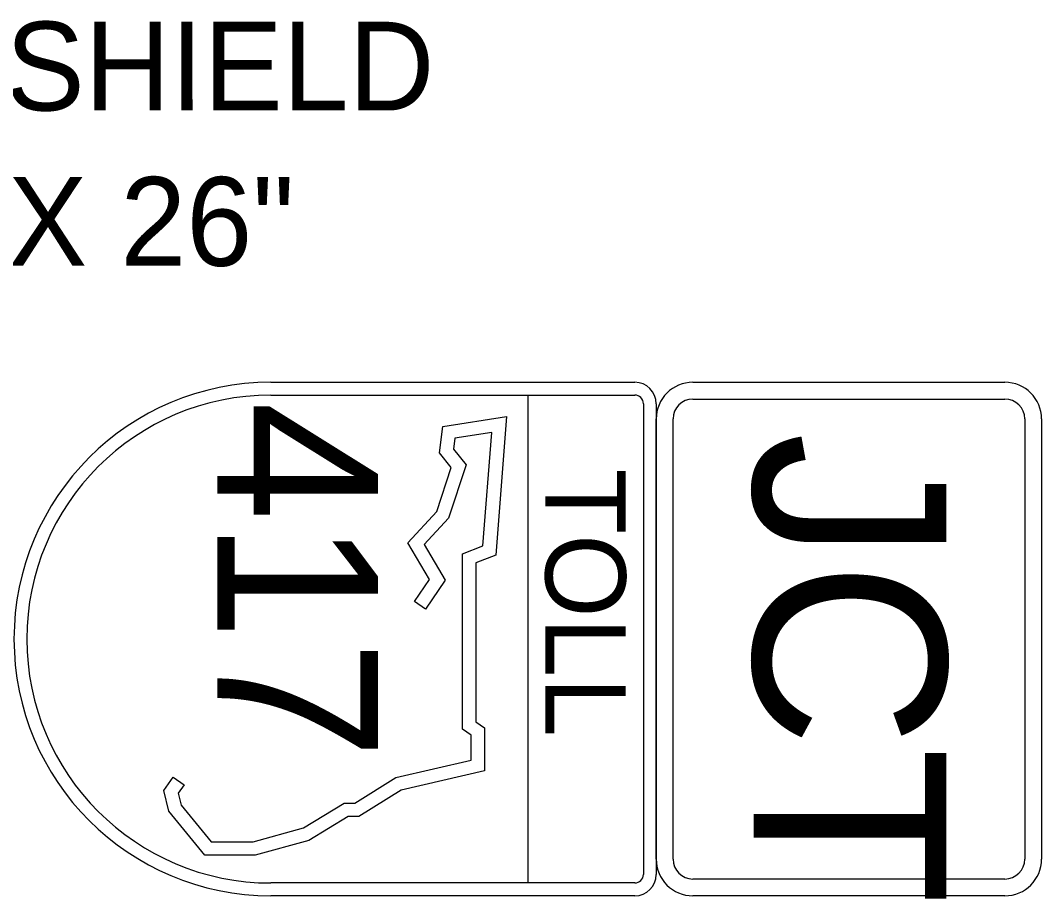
# Model space of a CAD drawing. Extents: x -830008.4 to -829992.7, y 1290284.1 to 1290294.4.
# Drawn here: x -830006.521 to -830005.716, y 1290287.565 to 1290288.258 of the extents above; entities that cross this region are included whole.
import ezdxf

# ---------------------------------------------------------------- set-up
doc = ezdxf.new("R2010")
doc.units = 0
doc.layers.add('1', color=7, linetype='Continuous')
doc.layers.add('SheetBorder_dp', color=7, linetype='Continuous')

msp = doc.modelspace()

# ---------------------------------------------------------------- linework, layer by layer
at = {"layer": 'SheetBorder_dp'}
for p, q in [((-830006.18833, 1290287.9375), (-830006.1383, 1290287.94528)), ((-830006.1383, 1290287.94528), (-830006.14674, 1290287.83592)), ((-830006.19091, 1290287.91656), (-830006.18833, 1290287.9375)), ((-830006.17884, 1290287.9283), (-830006.17991, 1290287.91963)), ((-830006.14984, 1290287.93281), (-830006.17884, 1290287.9283)), ((-830006.15675, 1290287.84335), (-830006.14984, 1290287.93281)), ((-830006.17991, 1290287.91963), (-830006.17013, 1290287.9072)), ((-830006.1819, 1290287.90511), (-830006.19091, 1290287.91656)), ((-830006.19317, 1290287.87048), (-830006.1819, 1290287.90511)), ((-830006.17013, 1290287.9072), (-830006.18385, 1290287.86501)), ((-830006.21611, 1290287.84572), (-830006.19317, 1290287.87048)), ((-830006.18385, 1290287.86501), (-830006.20304, 1290287.84431)), ((-830006.19901, 1290287.81663), (-830006.21611, 1290287.84572)), ((-830006.20304, 1290287.84431), (-830006.18654, 1290287.81623)), ((-830006.17302, 1290287.83702), (-830006.15675, 1290287.84335)), ((-830006.17302, 1290287.69877), (-830006.17302, 1290287.83702)), ((-830006.14674, 1290287.83592), (-830006.16247, 1290287.8298)), ((-830006.16247, 1290287.8298), (-830006.16247, 1290287.70437)), ((-830006.21073, 1290287.79929), (-830006.19901, 1290287.81663)), ((-830006.18654, 1290287.81623), (-830006.20199, 1290287.79338)), ((-830006.20199, 1290287.79338), (-830006.21073, 1290287.79929)), ((-830006.16247, 1290287.70437), (-830006.15548, 1290287.69964)), ((-830006.16603, 1290287.69404), (-830006.17302, 1290287.69877)), ((-830006.16603, 1290287.67427), (-830006.16603, 1290287.69404)), ((-830006.15548, 1290287.69964), (-830006.15548, 1290287.66589)), ((-830006.22532, 1290287.66049), (-830006.16603, 1290287.67427)), ((-830006.4083, 1290287.65036), (-830006.40109, 1290287.66076)), ((-830006.40109, 1290287.66076), (-830006.39242, 1290287.65475)), ((-830006.25766, 1290287.64036), (-830006.22532, 1290287.66049)), ((-830006.15548, 1290287.66589), (-830006.22123, 1290287.65061)), ((-830006.39242, 1290287.65475), (-830006.39695, 1290287.64823)), ((-830006.40437, 1290287.63395), (-830006.4083, 1290287.65036)), ((-830006.39695, 1290287.64823), (-830006.39468, 1290287.63876)), ((-830006.22123, 1290287.65061), (-830006.25465, 1290287.62981)), ((-830006.39468, 1290287.63876), (-830006.37107, 1290287.60996)), ((-830006.29828, 1290287.62078), (-830006.26604, 1290287.64036)), ((-830006.26604, 1290287.64036), (-830006.25766, 1290287.64036)), ((-830006.37606, 1290287.59941), (-830006.40437, 1290287.63395)), ((-830006.26309, 1290287.62981), (-830006.29407, 1290287.611)), ((-830006.25465, 1290287.62981), (-830006.26309, 1290287.62981)), ((-830006.33787, 1290287.60996), (-830006.29828, 1290287.62078)), ((-830006.37107, 1290287.60996), (-830006.33787, 1290287.60996)), ((-830006.29407, 1290287.611), (-830006.33645, 1290287.59941)), ((-830006.33645, 1290287.59941), (-830006.37606, 1290287.59941))]:
    msp.add_line(p, q, dxfattribs=at)
for points in [[(-830006.32393, 1290287.97228), (-830006.03705, 1290287.97228)], [(-830005.99125, 1290287.97228), (-830005.74536, 1290287.97228)], [(-830006.32393, 1290287.96216), (-830006.03705, 1290287.96216)], [(-830006.12143, 1290287.96216), (-830006.12143, 1290287.57741)], [(-830005.99125, 1290287.95903), (-830005.74534, 1290287.95903)], [(-830006.0303, 1290287.95541), (-830006.0303, 1290287.58416)], [(-830006.02018, 1290287.95541), (-830006.02018, 1290287.58416)], [(-830006.02018, 1290287.59621), (-830006.02018, 1290287.94336)], [(-830006.00692, 1290287.59621), (-830006.00692, 1290287.94336)], [(-830005.72969, 1290287.94336), (-830005.72969, 1290287.59621)], [(-830005.71643, 1290287.94336), (-830005.71643, 1290287.59621)], [(-830005.74534, 1290287.58054), (-830005.99125, 1290287.58054)], [(-830006.03705, 1290287.57741), (-830006.32393, 1290287.57741)], [(-830006.03705, 1290287.56728), (-830006.32393, 1290287.56728)], [(-830005.74536, 1290287.56728), (-830005.99125, 1290287.56728)]]:
    msp.add_lwpolyline(points, dxfattribs=at)
for centre, radius, start, end in [((-830006.32393, 1290287.76978), 0.2025, 90, 270), ((-830006.03705, 1290287.95541), 0.01687, 0, 90), ((-830005.99125, 1290287.94336), 0.02893, 90, 180), ((-830005.74536, 1290287.94336), 0.02893, 0, 90), ((-830006.32393, 1290287.76978), 0.19238, 90, 270), ((-830006.03705, 1290287.95541), 0.00675, 0, 90), ((-830005.99125, 1290287.94336), 0.01567, 90, 180), ((-830005.74536, 1290287.94336), 0.01567, 0, 89.9456), ((-830005.99125, 1290287.59621), 0.02893, 180, 270), ((-830005.99125, 1290287.59621), 0.01567, 180, 270), ((-830005.74536, 1290287.59621), 0.02893, 270, 0), ((-830005.74536, 1290287.59621), 0.01567, 270.0544, 0), ((-830006.03705, 1290287.58416), 0.01687, 270, 0), ((-830006.03705, 1290287.58416), 0.00675, 270, 0)]:
    msp.add_arc(centre, radius, start, end, dxfattribs=at)

# ---------------------------------------------------------------- texts
at = {"layer": '1'}
for s, p in [('TOLL SHIELD', (-830006.79324, 1290288.18662)), ('30" X 26"  ', (-830006.69447, 1290288.06412))]:
    msp.add_text(s, height=0.07, rotation=0.00437, dxfattribs=at).set_placement(p)
at = {"layer": 'SheetBorder_dp'}
for s, height, p in [('417', 0.126563, (-830006.36615, 1290287.95716)), ('JCT', 0.151875, (-830005.94346, 1290287.93271)), ('TOLL', 0.063281, (-830006.10751, 1290287.90422))]:
    msp.add_text(s, height=height, rotation=270, dxfattribs=at).set_placement(p)

doc.saveas('drawing.dxf')
